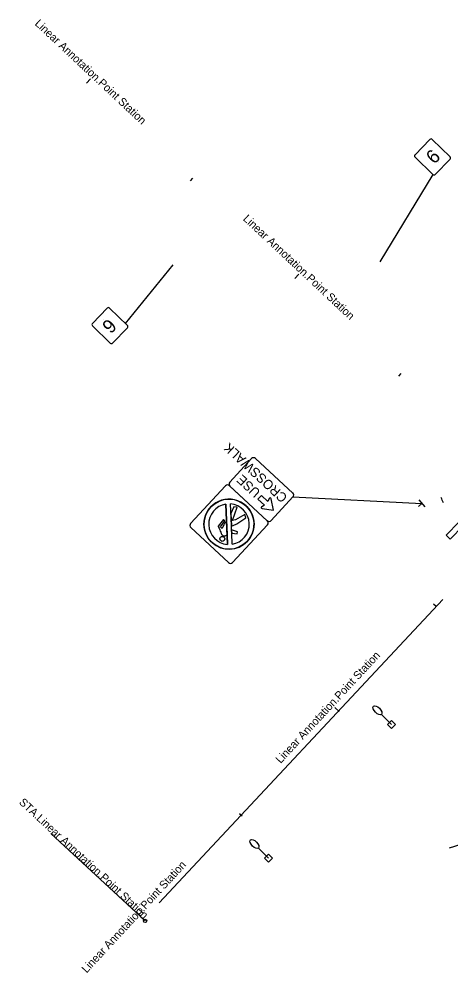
# Model space of a CAD drawing. Extents: x 1470334 to 1481646, y 379063 to 388330.
# Drawn here: x 1479996.1 to 1480147.4, y 379254 to 379587.8 of the extents above; entities that cross this region are included whole.
import ezdxf

# ---------------------------------------------------------------- set-up
doc = ezdxf.new("R2010")
doc.units = 0
for name, color, linetype in [('Default', 7, 'Continuous'), ('GK_Visualization', 7, 'Continuous'), ('SG_X_Poles', 7, 'Continuous'), ('SN_X_Private', 7, 'Continuous'), ('SV_X_Text_Description', 7, 'Continuous'), ('UT_X_Electric_Cells', 7, 'Continuous'), ('UT_X_Misc_Cells', 7, 'Continuous')]:
    doc.layers.add(name, color=color, linetype=linetype)

msp = doc.modelspace()

# ---------------------------------------------------------------- linework, layer by layer
at = {"layer": 'Default'}
for p, q in [((1480019.7, 379565.41), (1480021.07, 379566.87)), ((1480019.7, 379565.41), (1480021.07, 379566.87)), ((1480056.2, 379531.23), (1480057.02, 379532.11)), ((1480056.2, 379531.23), (1480057.02, 379532.11)), ((1480092.7, 379497.06), (1480094.07, 379498.52)), ((1480092.7, 379497.06), (1480094.07, 379498.52)), ((1480129.2, 379462.89), (1480130.02, 379463.77)), ((1480129.2, 379462.89), (1480130.02, 379463.77)), ((1480142.24, 379382.19), (1480141.36, 379383.01)), ((1480142.24, 379382.19), (1480141.36, 379383.01)), ((1480108.24, 379345.53), (1480106.77, 379346.89)), ((1480108.24, 379345.53), (1480106.77, 379346.89)), ((1480074.24, 379308.87), (1480073.36, 379309.68)), ((1480074.24, 379308.87), (1480073.36, 379309.68)), ((1480040.24, 379272.2), (1480007.25, 379302.8)), ((1480040.24, 379272.2), (1480007.25, 379302.8)), ((1480040.24, 379272.2), (1480038.77, 379273.56)), ((1480040.24, 379272.2), (1480038.77, 379273.56))]:
    msp.add_line(p, q, dxfattribs=at)
msp.add_circle((1480040.24, 379272.2), 0.6, dxfattribs=at)
msp.add_circle((1480040.24, 379272.2), 0.6, dxfattribs=at)
at = {"layer": 'GK_Visualization'}
msp.add_lwpolyline([(1480150.33, 379411.84), (1480151.75, 379410.43), (1480147.19, 379405.81), (1480145.76, 379407.21)], close=True, dxfattribs=at)
at = {"layer": 'SG_X_Poles'}
for p, q in [((1480126.59, 379340.92), (1480123.08, 379344.48)), ((1480083.47, 379294.13), (1480079.96, 379297.7))]:
    msp.add_line(p, q, dxfattribs=at)
for points in [[(1480126.58, 379339.51), (1480125.18, 379340.93), (1480126.6, 379342.33), (1480128.01, 379340.91)], [(1480083.46, 379292.72), (1480082.06, 379294.14), (1480083.48, 379295.55), (1480084.89, 379294.12)]]:
    msp.add_lwpolyline(points, close=True, dxfattribs=at)
for centre in [(1480121.68, 379345.91), (1480078.56, 379299.12)]:
    msp.add_ellipse(centre, major_axis=(-1.4, 1.42), ratio=0.5, dxfattribs=at)
at = {"layer": 'SN_X_Private'}
msp.add_arc((1480125.9, 379411.48), 20.16, 20.4277, 26.1207, dxfattribs=at)
at = {"layer": 'SV_X_Text_Description'}
for p, q in [((1480143.13, 379537.5), (1480143.13, 379537.5)), ((1480141.07, 379533.46), (1480122.46, 379502.84)), ((1480033.39, 379481.24), (1480050.11, 379501.81)), ((1480025.75, 379482.62), (1480025.75, 379482.62))]:
    msp.add_line(p, q, dxfattribs=at)
for points in [[(1480134.85, 379540.36), (1480140.02, 379545.69)], [(1480140.9, 379545.7), (1480147.11, 379539.67)], [(1480141.07, 379533.46), (1480134.86, 379539.49)], [(1480147.12, 379538.79), (1480141.95, 379533.47)], [(1480021.76, 379481.32), (1480026.93, 379486.64)], [(1480027.81, 379486.66), (1480034.02, 379480.62)], [(1480027.98, 379474.41), (1480021.78, 379480.45)], [(1480034.03, 379479.75), (1480028.86, 379474.43)]]:
    msp.add_lwpolyline(points, dxfattribs=at)
for centre, start, end in [((1480140.47, 379545.25), 45.8289, 135.8289), ((1480135.29, 379539.93), 135.8289, 225.8289), ((1480146.67, 379539.22), 315.8289, 45.8289), ((1480141.5, 379533.9), 225.8289, 315.8289), ((1480027.38, 379486.21), 45.8289, 135.8289), ((1480022.21, 379480.89), 135.8289, 225.8289), ((1480033.59, 379480.18), 315.8289, 45.8289), ((1480028.42, 379474.86), 225.8289, 315.8289)]:
    msp.add_arc(centre, 0.618, start, end, dxfattribs=at)
at = {"layer": 'UT_X_Electric_Cells'}
for p, q in [((1480081, 379421.11), (1480079.8, 379419.82)), ((1480079.8, 379419.82), (1480082.06, 379417.73)), ((1480083.74, 379420.02), (1480083.27, 379419.01)), ((1480085.24, 379415.98), (1480084.39, 379419.95)), ((1480092.07, 379420.57), (1480137.23, 379418.34)), ((1480136.18, 379419.55), (1480138.28, 379417.13)), ((1480069.08, 379403.98), (1480068.55, 379418.06)), ((1480071.36, 379417.1), (1480070.34, 379414.83)), ((1480071.36, 379417.1), (1480070.34, 379414.83)), ((1480070.84, 379412.34), (1480072.46, 379416.99)), ((1480070.84, 379412.34), (1480072.46, 379416.99)), ((1480072.46, 379416.99), (1480071.36, 379417.1)), ((1480072.46, 379416.99), (1480071.36, 379417.1)), ((1480082.07, 379417.72), (1480081.1, 379417.16)), ((1480081.22, 379416.53), (1480085.24, 379415.98)), ((1480082.06, 379417.73), (1480082.07, 379417.72)), ((1480082.75, 379418.29), (1480082.75, 379418.29)), ((1480137.23, 379418.34), (1480136.02, 379417.29)), ((1480070.34, 379414.83), (1480070.52, 379410.47)), ((1480075.15, 379414.39), (1480071.98, 379412.52)), ((1480075.15, 379414.39), (1480071.98, 379412.52)), ((1480072.38, 379411.12), (1480075.55, 379413.32)), ((1480072.38, 379411.12), (1480075.55, 379413.32)), ((1480075.55, 379413.32), (1480075.15, 379414.39)), ((1480075.55, 379413.32), (1480075.15, 379414.39)), ((1480067.73, 379412.65), (1480065.87, 379410.3)), ((1480067.73, 379412.65), (1480065.87, 379410.3)), ((1480065.87, 379410.3), (1480065.88, 379410.29)), ((1480065.87, 379410.3), (1480065.88, 379410.29)), ((1480066.71, 379410.07), (1480068.16, 379412.18)), ((1480066.71, 379410.07), (1480068.16, 379412.18)), ((1480067.23, 379409.55), (1480066.71, 379410.07)), ((1480067.23, 379409.55), (1480066.71, 379410.07)), ((1480068.16, 379412.18), (1480067.73, 379412.65)), ((1480068.16, 379412.18), (1480067.73, 379412.65)), ((1480068.95, 379407.44), (1480068.77, 379412)), ((1480070.52, 379410.39), (1480071.06, 379410.58)), ((1480070.52, 379410.39), (1480071.06, 379410.58)), ((1480070.52, 379410.47), (1480070.52, 379410.39)), ((1480071.98, 379412.52), (1480070.84, 379412.34)), ((1480071.98, 379412.52), (1480070.84, 379412.34)), ((1480071.06, 379410.58), (1480072.38, 379411.12)), ((1480071.06, 379410.58), (1480072.38, 379411.12)), ((1480068.95, 379407.3), (1480068.95, 379407.44)), ((1480072.63, 379408.42), (1480070.57, 379409.09)), ((1480072.63, 379408.42), (1480070.57, 379409.09)), ((1480070.57, 379409.09), (1480070.58, 379408.85)), ((1480070.62, 379407.92), (1480072.53, 379407.72)), ((1480070.62, 379407.92), (1480072.53, 379407.72)), ((1480072.53, 379407.72), (1480072.63, 379408.42)), ((1480072.53, 379407.72), (1480072.63, 379408.42)), ((1480146.94, 379297.73), (1480203.91, 379316.22))]:
    msp.add_line(p, q, dxfattribs=at)
for points in [[(1480069.94, 379425.78), (1480077.56, 379434.01)], [(1480078.95, 379434.06), (1480092.02, 379421.96)], [(1480068.44, 379424.46), (1480056.21, 379411.25)], [(1480083.06, 379412.28), (1480069.85, 379424.51)], [(1480083.06, 379412.28), (1480069.99, 379424.38)], [(1480083.26, 379419.02), (1480081, 379421.11)], [(1480092.07, 379420.57), (1480084.46, 379412.34)], [(1480068.54, 379418.06), (1480068.75, 379412.47), (1480068.76, 379412.47), (1480068.75, 379412.47), (1480068.95, 379407.44), (1480068.95, 379407.44)], [(1480070.58, 379408.85), (1480070.52, 379410.47), (1480070.31, 379415.71), (1480070.22, 379418.12)], [(1480056.26, 379409.84), (1480069.47, 379397.61)], [(1480070.88, 379397.66), (1480083.11, 379410.87)], [(1480068.95, 379407.44), (1480069.08, 379403.98)], [(1480068.95, 379407.44), (1480068.95, 379407.44)], [(1480070.77, 379404.05), (1480070.62, 379407.88), (1480070.57, 379408.85), (1480070.58, 379408.85)], [(1480070.58, 379408.85), (1480070.62, 379407.92), (1480070.62, 379407.92)]]:
    msp.add_lwpolyline(points, dxfattribs=at)
for centre, radius in [((1480069.65, 379411.05), 8.77), ((1480067.3, 379405.9), 0.864)]:
    msp.add_circle(centre, radius, dxfattribs=at)
for centre, radius, start, end in [((1480078.28, 379433.34), 0.989, 47.1998, 137.1998), ((1480069.17, 379423.78), 1, 47.1998, 137.1998), ((1480070.66, 379425.11), 0.989, 137.1998, 227.1998), ((1480069.65, 379411.05), 8.77, 317.1998, 137.1998), ((1480084.05, 379419.88), 0.342, 12.1205, 154.8376), ((1480091.35, 379421.24), 0.989, 317.1998, 47.1998), ((1480069.65, 379411.05), 8.77, 137.1998, 317.1998), ((1480069.65, 379411.05), 7.09, 99.0188, 265.3711), ((1480069.65, 379411.05), 7.09, 99.0188, 265.3711), ((1480069.65, 379411.05), 7.09, 279.0477, 85.4477), ((1480069.65, 379411.05), 7.09, 279.0477, 85.4477), ((1480081.27, 379416.87), 0.342, 119.562, 262.279), ((1480056.94, 379410.57), 1, 137.1998, 227.1998), ((1480083.73, 379413.01), 0.989, 227.1998, 317.1998), ((1480082.38, 379411.55), 1, 317.1998, 47.1998), ((1480068.7, 379408.96), 1.54, 279.2749, 279.3281), ((1480070.15, 379398.34), 1, 227.1998, 317.1998)]:
    msp.add_arc(centre, radius, start, end, dxfattribs=at)
for points in [[(1480065.88, 379410.29), (1480066.26, 379409.4), (1480066.85, 379407.99), (1480067.07, 379407.48), (1480067.17, 379407.34), (1480067.29, 379407.22), (1480067.59, 379406.95), (1480068.28, 379406.96), (1480068.69, 379407.17), (1480068.95, 379407.3)], [(1480065.88, 379410.29), (1480066.26, 379409.4), (1480066.85, 379407.99), (1480067.07, 379407.48), (1480067.17, 379407.34), (1480067.29, 379407.22), (1480067.59, 379406.95), (1480068.28, 379406.96), (1480068.69, 379407.17), (1480068.95, 379407.3)], [(1480068.77, 379412), (1480068.7, 379411.97), (1480068.51, 379411.86), (1480068.23, 379411.5), (1480068.01, 379411.14), (1480067.66, 379410.47), (1480067.43, 379410), (1480067.23, 379409.55)], [(1480068.77, 379412), (1480068.7, 379411.97), (1480068.51, 379411.86), (1480068.23, 379411.5), (1480068.01, 379411.14), (1480067.66, 379410.47), (1480067.43, 379410), (1480067.23, 379409.55)]]:
    msp.add_open_spline(points, degree=3, dxfattribs=at)
at = {"layer": 'UT_X_Misc_Cells'}
msp.add_line((1480144.56, 379384.7), (1480045.2, 379278.59), dxfattribs=at)

# ---------------------------------------------------------------- texts
at = {"layer": 'Default'}
for s, rotation, p in [('Linear Annotation.Point Station', 316.886, (1480001.37, 379585.99)), ('Linear Annotation.Point Station', 316.886, (1480001.37, 379585.99)), ('Linear Annotation.Point Station', 316.886, (1480074.37, 379517.65)), ('Linear Annotation.Point Station', 316.886, (1480074.37, 379517.65)), ('Linear Annotation.Point Station', 47.1589, (1480087.74, 379327.1)), ('Linear Annotation.Point Station', 47.1589, (1480087.74, 379327.1)), (' STA. ', 317.1589, (1479995.09, 379314.12)), (' STA. ', 317.1589, (1479995.09, 379314.12)), ('Linear Annotation.Point Station', 317.1589, (1480001.93, 379307.78)), ('Linear Annotation.Point Station', 317.1589, (1480001.93, 379307.78)), ('Linear Annotation.Point Station', 47.1589, (1480019.74, 379253.78)), ('Linear Annotation.Point Station', 47.1589, (1480019.74, 379253.78))]:
    msp.add_text(s, height=2.8, rotation=rotation, dxfattribs=at).set_placement(p)
at = {"layer": 'SV_X_Text_Description'}
for rotation, p in [(45.8289, (1480140.38, 379535.53)), (225.8289, (1480028.5, 379484.58))]:
    msp.add_text(' 6', height=4.776, rotation=rotation, dxfattribs=at).set_placement(p)
at = {"layer": 'UT_X_Electric_Cells'}
for s, p in [('CROSSWALK', (1480090.39, 379420.69)), ('USE', (1480080.9, 379422.47))]:
    msp.add_text(s, height=3.296, rotation=137.1998, dxfattribs=at).set_placement(p)

doc.saveas('drawing.dxf')
